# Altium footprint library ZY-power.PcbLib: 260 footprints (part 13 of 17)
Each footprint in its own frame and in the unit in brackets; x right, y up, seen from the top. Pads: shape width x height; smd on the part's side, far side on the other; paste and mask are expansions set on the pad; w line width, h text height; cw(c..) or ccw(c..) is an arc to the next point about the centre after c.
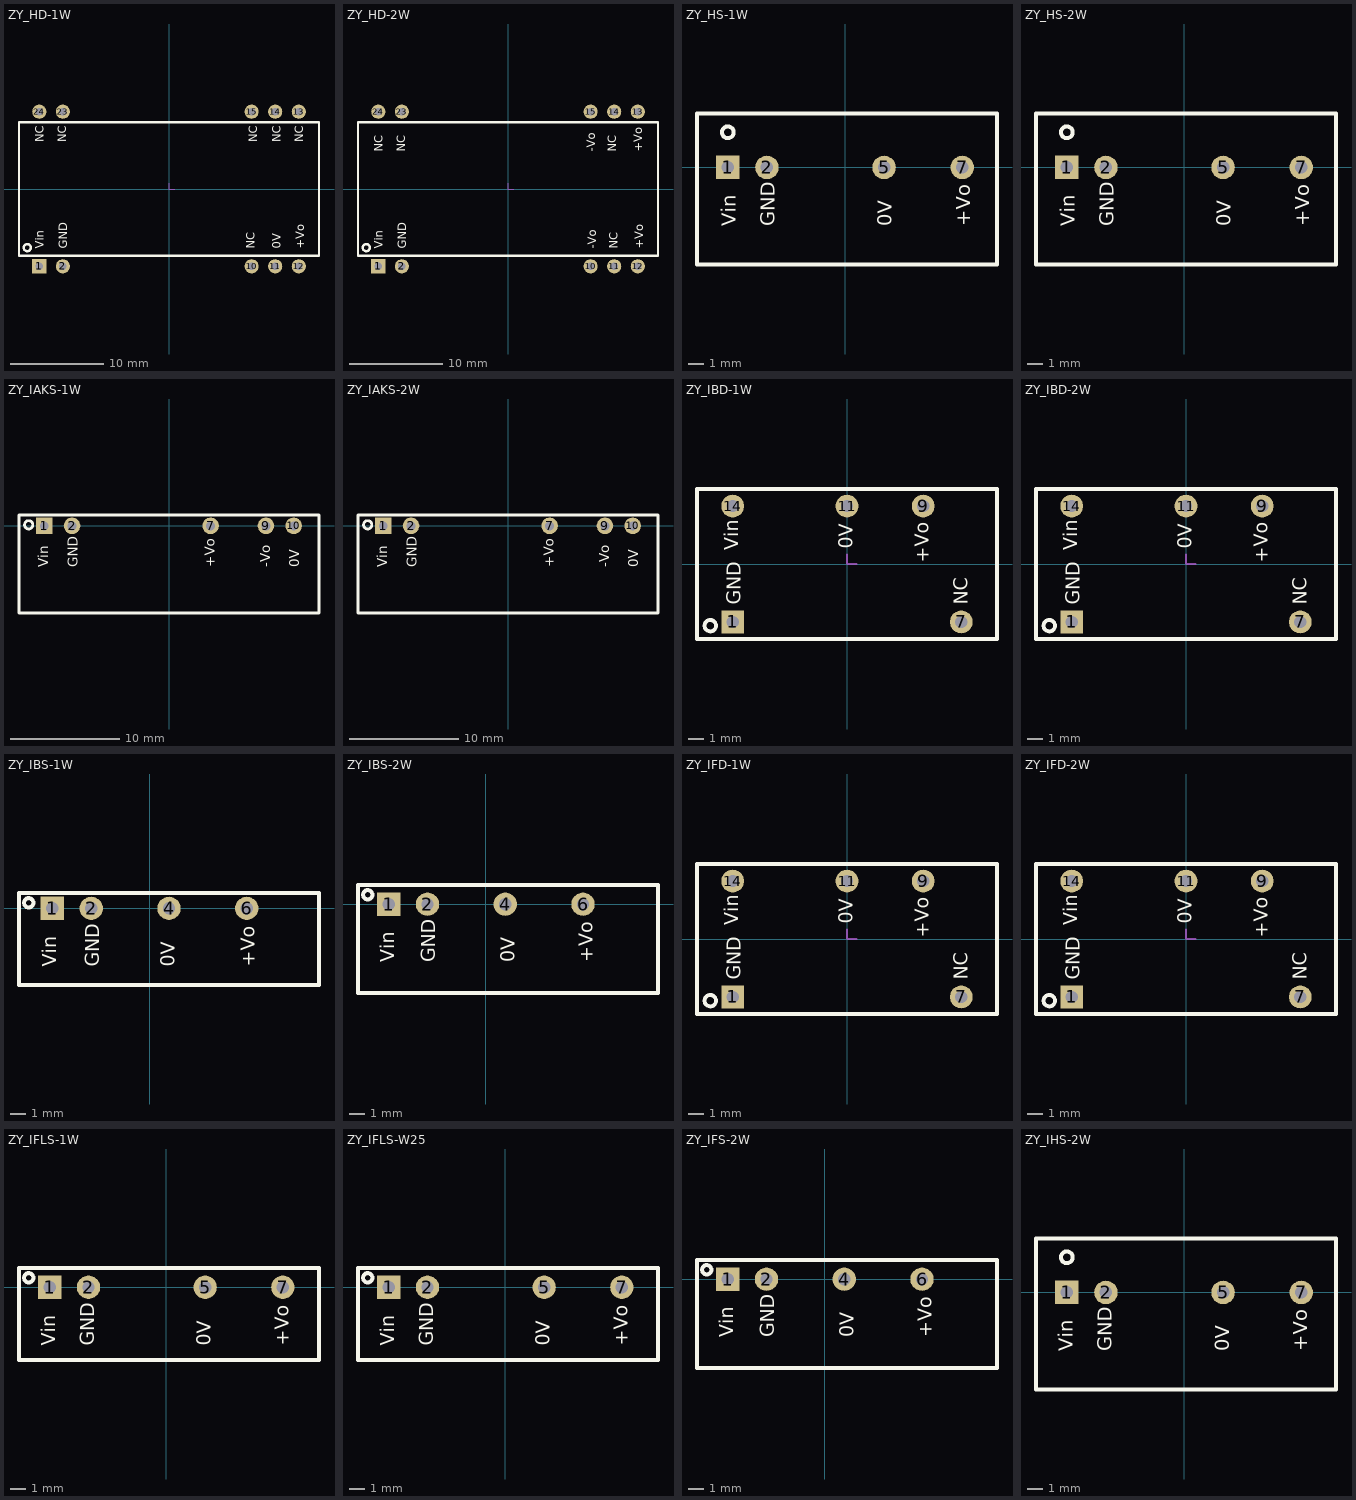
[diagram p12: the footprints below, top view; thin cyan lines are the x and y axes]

## ZY_HD-1W [mil]
pads (10):
  rect 60x60 hole 32: 1(-550,-327.76)
  round 60 hole 32: 2(-450,-327.76) 10(350,-327.76) 11(450,-327.76) 12(550,-327.76) 13(550,327.76) 14(450,327.76) 15(350,327.76) 23(-450,327.76) 24(-550,327.76)
Top Overlay:
  circle w10: c-601,-248.46 r15
  lines w10: -636,-283.46 -636,283.46 635.65,283.46 635.65,-283.46 -636,-283.46
  text "Vin" at -531,-252.76 h36
  text "GND" at -431,-252.76 h36
  text "NC" at 364,-252.76 h36
  text "0V" at 474,-252.76 h36
  text "+Vo" at 574,-252.76 h36
  text "NC" at 374,197.76 h36
  text "NC" at 474,197.76 h36
  text "NC" at 569,197.76 h36
  text "NC" at -436,197.76 h36
  text "NC" at -531,197.76 h36
Mechanical 15:
  lines w5: 0,25 0,0 25,0

## ZY_HD-2W [mil]
pads (10):
  rect 60x60 hole 32: 1(-550,-327.76)
  round 60 hole 32: 2(-450,-327.76) 10(350,-327.76) 11(450,-327.76) 12(550,-327.76) 13(550,327.76) 14(450,327.76) 15(350,327.76) 23(-450,327.76) 24(-550,327.76)
Top Overlay:
  circle w10: c-601,-248.46 r15
  lines w10: -636,-283.46 -636,283.46 635.65,283.46 635.65,-283.46 -636,-283.46
  text "+Vo" at 569,157.76 h36
  text "-Vo" at 369,157.76 h36
  text "NC" at 459,157.76 h36
  text "NC" at 464,-252.76 h36
  text "-Vo" at 374,-252.76 h36
  text "Vin" at -531,-252.76 h36
  text "GND" at -431,-252.76 h36
  text "+Vo" at 574,-252.76 h36
  text "NC" at -436,157.76 h36
  text "NC" at -531,157.76 h36
Mechanical 15:
  lines w5: 0,25 0,0 25,0

## ZY_HS-1W [mil]
pads (4):
  rect 60x60 hole 32: 1(-300,0)
  round 60 hole 32: 2(-200,0) 5(99.74,0) 7(300,0)
Top Overlay:
  circle w10: c-300,90 r15
  lines w10: 388.72,135.83 388.72,-248.03 -379,-248.03 -379,137.8 388.72,137.8
  text "Vin" at -280,-150 h36
  text "GND" at -180,-150 h36
  text "0V" at 120,-150 h36
  text "+Vo" at 320,-150 h36

## ZY_HS-2W [mil]
pads (4):
  rect 60x60 hole 32: 1(-300,0)
  round 60 hole 32: 2(-200,0) 5(99.74,0) 7(300,0)
Top Overlay:
  circle w10: c-300,90 r15
  lines w10: 388.72,135.83 388.72,-248.03 -379,-248.03 -379,137.8 388.72,137.8
  text "+Vo" at 320,-150 h36
  text "0V" at 120,-150 h36
  text "GND" at -180,-150 h36
  text "Vin" at -280,-150 h36

## ZY_IAKS-1W [mil] "定压输入隔离稳压双输出"
height 452.76
pads (5):
  rect 60x60 hole 32.01: 1(-450,0)
  round 60 hole 32.01: 2(-350,0) 7(150,0) 9(350,0) 10(450,0)
Top Overlay:
  circle w10: c-506.34,3.66 r15
  lines w10: -541.34,-314.96 -541.34,38.66 -540.63,39.37 541.34,39.37 541.34,-314.96 -541.34,-314.96
  text "0V" at 470,-150 h36
  text "-Vo" at 365,-150 h36
  text "+Vo" at 165,-150 h36
  text "GND" at -330,-150 h36
  text "Vin" at -435,-150 h36

## ZY_IAKS-2W [mil]
pads (5):
  rect 60x60 hole 32.01: 1(-450,0)
  round 60 hole 32.01: 2(-350,0) 7(150,0) 9(350,0) 10(450,0)
Top Overlay:
  circle w10: c-506.34,3.66 r15
  lines w10: -541.34,-314.96 -541.34,38.66 -540.63,39.37 541.34,39.37 541.34,-314.96 -541.34,-314.96
  text "0V" at 470,-150 h36
  text "-Vo" at 365,-150 h36
  text "+Vo" at 165,-150 h36
  text "GND" at -330,-150 h36
  text "Vin" at -435,-150 h36

## ZY_IBD-1W [mil]
height 318.9
pads (5):
  rect 60x60 hole 32: 1(-300,-151.97)
  round 60 hole 32: 7(300,-151.97) 9(200,151.97) 11(0,151.97) 14(-300,151.97)
Top Overlay:
  circle w10: c-358.7,-161.85 r15
  lines w10: -393.7,-196.85 -393.7,196.85 393.7,196.85 393.7,-196.85 -393.7,-196.85
  text "Vin" at -285,35.51 h36
  text "0V" at 15,40.14 h36
  text "+Vo" at 215,3.81 h36
  text "NC" at 316.3,-106.85 h36
  text "GND" at -278.7,-106.85 h36
Mechanical 15:
  lines w5: 0,25 0,0 25,0

## ZY_IBD-2W [mil]
pads (5):
  rect 60x60 hole 32: 1(-300,-151.97)
  round 60 hole 32: 7(300,-151.97) 9(200,151.97) 11(0,151.97) 14(-300,151.97)
Top Overlay:
  circle w10: c-358.7,-161.85 r15
  lines w10: -393.7,-196.85 -393.7,196.85 393.7,196.85 393.7,-196.85 -393.7,-196.85
  text "Vin" at -285,35.51 h36
  text "0V" at 15,40.14 h36
  text "+Vo" at 215,3.81 h36
  text "NC" at 316.3,-106.85 h36
  text "GND" at -278.7,-106.85 h36
Mechanical 15:
  lines w5: 0,25 0,0 25,0

## ZY_IBS-1W [mil] "定压输入隔离稳压单输出"
height 393.7
pads (4):
  rect 60x60 hole 32.01: 1(-250,0)
  round 60 hole 32.01: 2(-150,0) 4(50,0) 6(250,0)
Top Overlay:
  circle w10: c-310.83,14.37 r12
  lines w10: -335.83,-196.85 -335.83,39.37 435.83,39.37 435.83,-196.85 -335.83,-196.85
  text "+Vo" at 270,-150 h36
  text "0V" at 65,-150 h36
  text "GND" at -130,-150 h36
  text "Vin" at -240,-150 h36

## ZY_IBS-2W [mil]
pads (4):
  rect 60x60 hole 32: 1(-250,0)
  round 60 hole 32: 2(-150,0) 4(50,0) 6(250,0)
Top Overlay:
  circle w10: c-303.74,24.21 r12
  lines w10: -328.74,-228.35 -328.74,49.21 442.91,49.21 442.91,-228.35 -328.74,-228.35
  text "+Vo" at 275,-150 h36
  text "0V" at 75,-150 h36
  text "GND" at -130,-150 h36
  text "Vin" at -235,-150 h36

## ZY_IFD-1W [mil]
height 318.9
pads (5):
  rect 60x60 hole 32: 1(-300,-151.97)
  round 60 hole 32: 7(300,-151.97) 9(200,151.97) 11(0,151.97) 14(-300,151.97)
Top Overlay:
  circle w10: c-358.7,-161.85 r15
  lines w10: -393.7,-196.85 393.7,-196.85 393.7,196.85 -393.7,196.85 -393.7,-196.85
  text "GND" at -278.7,-106.85 h36
  text "NC" at 316.3,-106.85 h36
  text "+Vo" at 215,3.81 h36
  text "0V" at 15,40.14 h36
  text "Vin" at -285,35.51 h36
Mechanical 15:
  lines w5: 0,25 0,0 25,0

## ZY_IFD-2W [mil]
pads (5):
  rect 60x60 hole 32: 1(-300,-151.97)
  round 60 hole 32: 7(300,-151.97) 9(200,151.97) 11(0,151.97) 14(-300,151.97)
Top Overlay:
  circle w10: c-358.7,-161.85 r15
  lines w10: -393.7,-196.85 393.7,-196.85 393.7,196.85 -393.7,196.85 -393.7,-196.85
  text "GND" at -278.7,-106.85 h36
  text "NC" at 316.3,-106.85 h36
  text "+Vo" at 215,3.81 h36
  text "0V" at 15,40.14 h36
  text "Vin" at -285,35.51 h36
Mechanical 15:
  lines w5: 0,25 0,0 25,0

## ZY_IFLS-1W [mil]
pads (4):
  rect 60x60 hole 32: 1(-300,0)
  round 60 hole 32: 2(-200,0) 5(100,0) 7(300,0)
Top Overlay:
  circle w10: c-353.74,24.21 r12
  lines w10: -378.74,-187.01 -378.74,49.21 392.91,49.21 392.91,-187.01 -378.74,-187.01
  text "+Vo" at 315,-150 h36
  text "0V" at 115,-150 h36
  text "GND" at -185,-150 h36
  text "Vin" at -285,-150 h36

## ZY_IFLS-W25 [mil]
pads (4):
  rect 60x60 hole 32: 1(-300,0)
  round 60 hole 32: 2(-200,0) 5(100,0) 7(300,0)
Top Overlay:
  circle w10: c-353.74,24.21 r12
  lines w10: -378.74,-187.01 392.91,-187.01 392.91,49.21 -378.74,49.21 -378.74,-187.01
  text "Vin" at -285,-150 h36
  text "GND" at -185,-150 h36
  text "0V" at 115,-150 h36
  text "+Vo" at 315,-150 h36

## ZY_IFS-2W [mil]
pads (4):
  rect 60x60 hole 32: 1(-250,0)
  round 60 hole 32: 2(-150,0) 4(50,0) 6(250,0)
Top Overlay:
  circle w10: c-303.74,24.21 r12
  lines w10: -328.74,-228.35 442.91,-228.35 442.91,49.21 -328.74,49.21 -328.74,-228.35
  text "Vin" at -235,-150 h36
  text "GND" at -130,-150 h36
  text "0V" at 75,-150 h36
  text "+Vo" at 275,-150 h36

## ZY_IHS-2W [mil]
pads (4):
  rect 60x60 hole 32: 1(-300,0)
  round 60 hole 32: 2(-200,0) 5(99.74,0) 7(300,0)
Top Overlay:
  circle w10: c-300,90 r15
  lines w10: 388.72,135.83 388.72,-248.03 -379,-248.03 -379,137.8 388.72,137.8
  text "Vin" at -285,-150 h36
  text "GND" at -185,-150 h36
  text "0V" at 115,-150 h36
  text "+Vo" at 315,-150 h36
